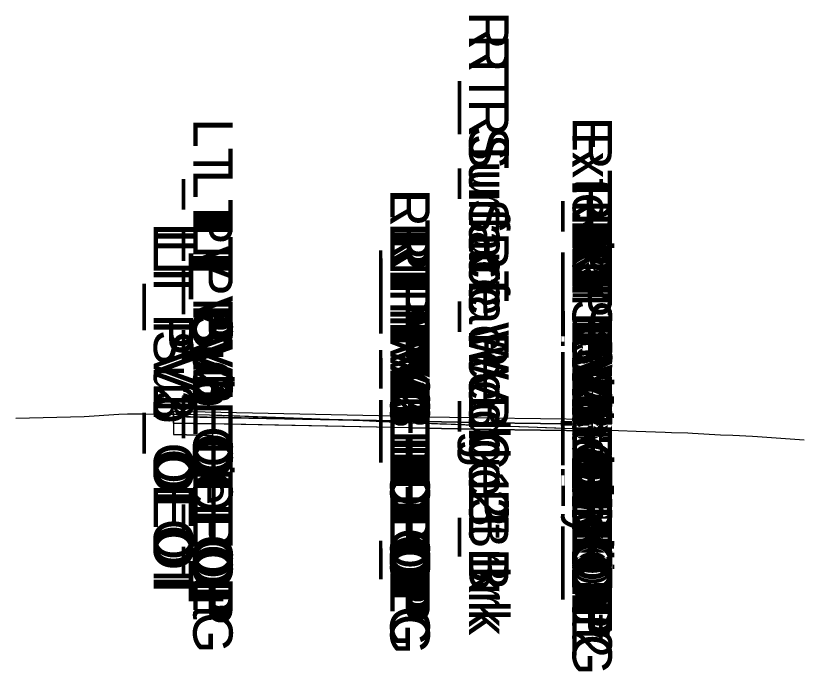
# Model space of a CAD drawing. Extents: x -26 to 3240, y -10 to 12522.
# Drawn here: x 2200 to 2240, y 4989.43 to 5022.67 of the extents above; entities that cross this region are included whole.
import ezdxf

# ---------------------------------------------------------------- set-up
doc = ezdxf.new("R2010")
doc.units = 0
for name, color, linetype in [('Default', 7, 'Continuous'), ('Exist CMT Pavement', 7, 'Continuous'), ('Exist XS Ground Line', 7, 'Continuous'), ('Prop CMT DNC', 7, 'Continuous'), ('Prop CMT Pvmt Course 1', 7, 'Continuous'), ('Prop CMT Pvmt Course 1 Wedge', 7, 'Continuous'), ('Prop CMT Pvmt Course 2', 7, 'Continuous'), ('Prop CMT Pvmt Course 2 Wedge', 7, 'Continuous'), ('Prop CMT Pvmt Course 3', 7, 'Continuous'), ('Prop CMT Pvmt Course 3 Wedge', 7, 'Continuous'), ('Prop CMT Pvmt Surface', 7, 'Continuous'), ('Prop CMT Pvmt Wedge Surface 1', 7, 'Continuous'), ('Prop CMT Pvmt Wedge Surface 2', 7, 'Continuous'), ('Prop CMT Pvmt Wedge Surface 3', 7, 'Continuous'), ('Prop CMT Shear Line', 7, 'Continuous'), ('Prop CMT Subgrade Earthwork', 7, 'Continuous'), ('Scratch_Level_0', 7, 'Continuous')]:
    doc.layers.add(name, color=color, linetype=linetype)

msp = doc.modelspace()

# ---------------------------------------------------------------- linework, layer by layer
at = {"layer": 'Exist CMT Pavement'}
for points in [[(2219.998, 5002.044), (2210.001, 5002.422)], [(2220.001, 5002.044), (2229.242, 5001.701)]]:
    msp.add_lwpolyline(points, dxfattribs=at)
at = {"layer": 'Exist XS Ground Line'}
msp.add_lwpolyline([(2200, 5002.273), (2203.464, 5002.35), (2205.221, 5002.478), (2205.674, 5002.483), (2206.514, 5002.48), (2207.712, 5002.468), (2208.347, 5002.463), (2209.114, 5002.456), (2209.835, 5002.428), (2210.54, 5002.401), (2211.624, 5002.363), (2213.336, 5002.303), (2213.907, 5002.283), (2215, 5002.243), (2216.139, 5002.202), (2217.611, 5002.146), (2218.947, 5002.089), (2220.145, 5002.038), (2220.507, 5002.022), (2220.668, 5002.015), (2221.519, 5001.977), (2221.714, 5001.972), (2222.831, 5001.934), (2224.534, 5001.878), (2226.007, 5001.825), (2226.879, 5001.793), (2227.324, 5001.776), (2228.709, 5001.722), (2230.129, 5001.667), (2230.584, 5001.649), (2231.467, 5001.614), (2232.942, 5001.557), (2233.271, 5001.546), (2234.087, 5001.518), (2234.336, 5001.502), (2235.744, 5001.43), (2236.372, 5001.402), (2237.374, 5001.358), (2237.624, 5001.34), (2240, 5001.17)], dxfattribs=at)
at = {"layer": 'Prop CMT DNC'}
msp.add_lwpolyline([(2229.243, 5001.042), (2229.243, 5002.542)], dxfattribs=at)
at = {"layer": 'Prop CMT Pvmt Course 1'}
for points in [[(2220, 5002.358), (2208, 5002.598)], [(2208, 5002.598), (2208, 5002.348)], [(2208, 5002.348), (2210, 5002.307)], [(2210, 5002.307), (2210, 5002.308)], [(2210, 5002.308), (2220, 5002.108)], [(2220, 5002.107), (2220, 5002.358)], [(2220, 5002.358), (2224, 5002.278), (2229.243, 5002.209)], [(2220, 5002.107), (2220, 5002.358)], [(2220, 5002.108), (2220, 5002.107), (2220, 5002.107)], [(2229.243, 5001.959), (2224, 5002.028), (2220, 5002.108)], [(2220, 5002.108), (2220, 5002.107), (2220, 5002.107)], [(2229.243, 5002.209), (2229.243, 5001.959), (2229.243, 5001.959), (2229.243, 5001.959)]]:
    msp.add_lwpolyline(points, dxfattribs=at)
at = {"layer": 'Prop CMT Pvmt Course 1 Wedge'}
for points in [[(2220, 5002.108), (2210, 5002.308)], [(2224, 5002.028), (2220, 5002.108)], [(2220, 5002.108), (2229.243, 5001.959)], [(2229.243, 5001.959), (2224, 5002.028)]]:
    msp.add_lwpolyline(points, dxfattribs=at)
at = {"layer": 'Prop CMT Pvmt Course 2'}
for points in [[(2210, 5002.307), (2208, 5002.348)], [(2208, 5002.348), (2208, 5002.014)], [(2208, 5002.014), (2210, 5001.974)], [(2210, 5001.974), (2210, 5002.307)], [(2229.243, 5001.626), (2229.243, 5001.626), (2229.243, 5001.959), (2229.243, 5001.959)], [(2229.243, 5001.959), (2229.243, 5001.626)]]:
    msp.add_lwpolyline(points, dxfattribs=at)
at = {"layer": 'Prop CMT Pvmt Course 2 Wedge'}
for points in [[(2220, 5002.107), (2210, 5002.307)], [(2224, 5002.028), (2220, 5002.107)], [(2220, 5002.107), (2229.243, 5001.959)], [(2229.243, 5001.959), (2224, 5002.028)]]:
    msp.add_lwpolyline(points, dxfattribs=at)
at = {"layer": 'Prop CMT Pvmt Course 3'}
for points in [[(2210, 5001.974), (2208, 5002.014)], [(2208, 5002.014), (2208, 5001.431)], [(2210, 5001.391), (2210, 5001.974)], [(2229.243, 5001.626), (2229.243, 5001.626), (2229.243, 5001.042), (2229.243, 5001.042)], [(2229.243, 5001.042), (2229.243, 5001.626)], [(2208, 5001.431), (2210, 5001.391)]]:
    msp.add_lwpolyline(points, dxfattribs=at)
at = {"layer": 'Prop CMT Pvmt Course 3 Wedge'}
for points in [[(2220, 5001.774), (2210, 5001.974)], [(2224, 5001.694), (2220, 5001.774)], [(2220, 5001.774), (2229.243, 5001.626)], [(2229.243, 5001.626), (2224, 5001.694)]]:
    msp.add_lwpolyline(points, dxfattribs=at)
at = {"layer": 'Prop CMT Pvmt Surface'}
for points in [[(2220, 5002.358), (2208, 5002.598)], [(2220, 5002.358), (2224, 5002.278), (2229.243, 5002.209)]]:
    msp.add_lwpolyline(points, dxfattribs=at)
at = {"layer": 'Prop CMT Pvmt Wedge Surface 1'}
for points in [[(2208, 5002.348), (2208, 5002.598)], [(2210, 5002.307), (2208, 5002.348)], [(2220, 5002.108), (2210, 5002.308)], [(2210, 5002.308), (2210, 5002.307)], [(2220, 5002.108), (2224, 5002.028), (2229.243, 5001.959)], [(2229.243, 5001.959), (2229.243, 5002.209)], [(2229.243, 5001.959), (2229.243, 5001.959), (2229.243, 5001.959)]]:
    msp.add_lwpolyline(points, dxfattribs=at)
at = {"layer": 'Prop CMT Pvmt Wedge Surface 2'}
for points in [[(2208, 5002.348), (2208, 5002.598)], [(2220, 5002.107), (2208, 5002.348)], [(2220, 5002.107), (2224, 5002.028), (2229.243, 5001.959)], [(2229.243, 5001.959), (2229.243, 5002.209)]]:
    msp.add_lwpolyline(points, dxfattribs=at)
at = {"layer": 'Prop CMT Pvmt Wedge Surface 3'}
for points in [[(2208, 5002.014), (2208, 5002.598)], [(2220, 5001.774), (2208, 5002.014)], [(2229.243, 5001.626), (2229.243, 5002.209)], [(2220, 5001.774), (2224, 5001.694), (2229.243, 5001.626)]]:
    msp.add_lwpolyline(points, dxfattribs=at)
at = {"layer": 'Prop CMT Shear Line'}
msp.add_lwpolyline([(2229.243, 5006.042), (2229.243, 4996.042)], dxfattribs=at)
at = {"layer": 'Prop CMT Subgrade Earthwork'}
for points in [[(2210, 5001.391), (2210.001, 5002.422)], [(2229.243, 5001.042), (2229.242, 5001.701)], [(2229.243, 5001.042), (2229.253, 5001.701)], [(2210, 5001.391), (2208, 5001.431)], [(2229.243, 5001.042), (2229.243, 5001.042)]]:
    msp.add_lwpolyline(points, dxfattribs=at)

# ---------------------------------------------------------------- texts
at = {"layer": 'Default'}
msp.add_text('-', height=0.0001, dxfattribs=at).set_placement((2200, 5000))
at = {"layer": 'Scratch_Level_0'}
for s, p in [('RT_ Surface Wedge2_Brk', (2223, 5022.894)), ('RT_Surface Wedge3_Brk', (2223, 5021.741)), ('RT_Surface Brk Pt', (2223, 5018.466)), ('LT_PV_Sub_Tie_Out', (2209.001, 5017.477)), ('Exterior Boundary', (2228.253, 5017.559)), ('RT_PV_Sub_Tie_Out', (2228.242, 5016.803)), ('LT_PV_OEEOP_EG', (2209.001, 5014.878)), ('LT_PV_IEEOP_EG', (2218.998, 5013.855)), ('RT_PV_IEEOP_EG', (2219.001, 5013.902)), ('RT_PV_OEEOP_EG', (2228.242, 5014.205)), ('RT_SL_Pt1', (2228.243, 5013.365)), ('LT_PV2_OEEOP', (2209, 5013)), ('LT_PV3_OEEOP', (2209, 5012.667)), ('RT_PV2_OEEOP', (2228.243, 5012.699)), ('LT_PV1_OEEOP', (2209, 5012.433)), ('RT_PV3_OEEOP', (2228.243, 5012.366)), ('LT_PV2_OEOT', (2207, 5012.174)), ('LT_PV1_OEOT', (2207, 5011.857)), ('LT_PV3_OEOT', (2207, 5011.841)), ('LT_Sub_OEEOP', (2209, 5012.178)), ('RT_PV2_IEEOP', (2219, 5012.202)), ('LT_PV2_IEEOP', (2219, 5012.155)), ('RT_PV3_IEEOP', (2219, 5011.869)), ('RT_PV1_OEEOP', (2228.243, 5012.132)), ('RT_Sub_OEEOP', (2228.243, 5011.877)), ('RT_PV2_OEOT', (2228.243, 5011.833)), ('LT_PV3_IEEOP', (2219, 5011.821)), ('RT_PV1_IEEOP', (2219, 5011.635)), ('LT_PV1_IEEOP', (2219, 5011.588)), ('RT_PV_C1 Brk', (2223, 5011.713)), ('RT_SL_Label', (2228.243, 5011.818)), ('RT_PV1_OEOT', (2228.243, 5011.516)), ('RT_PV3_OEOT', (2228.243, 5011.5)), ('LT_Sub_OEOT', (2207, 5011.352)), ('RT_Slope_Fill', (2228.253, 5011.228)), ('RT_Sub_OEOT', (2228.243, 5011.011)), ('PV2_PGL', (2219, 5008.202)), ('PV1_PGL', (2219, 5007.885)), ('RT_SL_Pt2', (2228.243, 5003.932))]:
    msp.add_text(s, height=2, rotation=270, dxfattribs=at).set_placement(p)

doc.saveas('drawing.dxf')
